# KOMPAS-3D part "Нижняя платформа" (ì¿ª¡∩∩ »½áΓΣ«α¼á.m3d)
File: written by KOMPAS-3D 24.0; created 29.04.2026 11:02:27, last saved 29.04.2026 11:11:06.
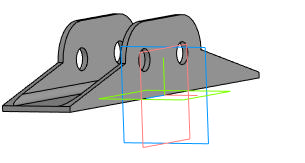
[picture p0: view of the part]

Document properties: Автор: USG_411; Полное имя файла: C:\Users\USG_411\Desktop\ИА-2904_411-12\Нижняя платформа.m3d

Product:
- Part/product: Нижняя платформа
    Масса: 0.370663

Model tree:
1. Эскиз:1
2. Элемент выдавливания:1
     Расстояние 2 = 40
3. Эскиз:2  (with: Ребро.Элемент выдавливания:1)
4. Элемент выдавливания:2
     Расстояние 1 = 100; Расстояние 2 = 100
